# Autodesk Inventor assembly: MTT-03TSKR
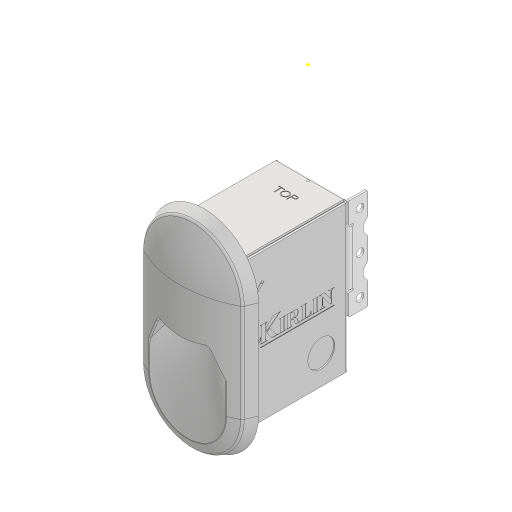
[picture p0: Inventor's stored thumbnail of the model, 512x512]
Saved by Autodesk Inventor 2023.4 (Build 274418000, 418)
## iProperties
Created: 2024-02
Part Number: MTT-03TSKR
Document SubType Name: Assembly
Designer: sjaafar
Author: sjaafar
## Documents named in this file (3)
- X:\Revit Files\0000-Un-Zipped\LED\MTT-03TSK\MTT-03TSKR.iam
- X:\INVENTOR\_NPD DIRECTORY\TASK WALL MOUNT\PRODUCTION\904003-XX-XX.iam
- X:\INVENTOR\_NPD DIRECTORY\TASK WALL MOUNT\PRODUCTION\902001-00-00.iam
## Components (2 placed, 2 different names)
1. 904003-XX-XX:1 [sub-assembly] — Mate:1, Flush:1, Flush:2, Rigid:1
2. 902001-00-00:1 [sub-assembly] — Rigid:1
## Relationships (4: Flush 2, Mate 1, WeldJoint 1)
- Mate:1: 904003-XX-XX:1
- Flush:1: 904003-XX-XX:1
- Flush:2: 904003-XX-XX:1
- Rigid:1 [WeldJoint]: 904003-XX-XX:1 ↔ 902001-00-00:1
